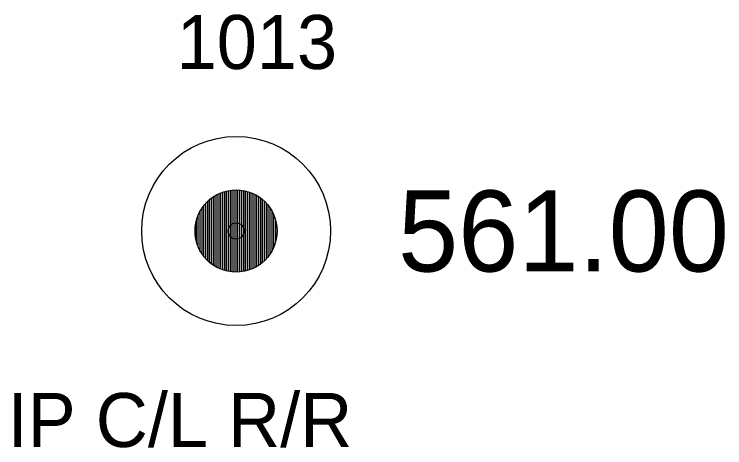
# Model space of a CAD drawing. Extents: x 1789242 to 1794757, y 908627 to 913936.
# Drawn here: x 1794743.37 to 1794756.54, y 912645.09 to 912653.12 of the extents above; entities that cross this region are included whole.
import ezdxf

# ---------------------------------------------------------------- set-up
doc = ezdxf.new("R2010")
doc.units = 0
for name, color, linetype in [('RD_EX_DV_Prop_txCode', 7, 'Continuous'), ('RD_EX_DV_PropPin', 7, 'Continuous'), ('RD_EX_TX_DV_Prop_ELEV', 7, 'Continuous'), ('RD_SMD_Locator', 7, 'Continuous')]:
    doc.layers.add(name, color=color, linetype=linetype)

msp = doc.modelspace()

# ---------------------------------------------------------------- linework, layer by layer
at = {"layer": 'RD_EX_DV_PropPin'}
for p, q in [((1794747.233, 912648.387), (1794747.233, 912649.828)), ((1794747.268, 912648.376), (1794747.268, 912649.839)), ((1794747.303, 912648.367), (1794747.303, 912649.848)), ((1794747.338, 912648.36), (1794747.338, 912649.856)), ((1794747.373, 912648.354), (1794747.373, 912649.861)), ((1794747.408, 912648.35), (1794747.408, 912649.865)), ((1794747.443, 912648.347), (1794747.443, 912649.868)), ((1794747.478, 912648.347), (1794747.478, 912649.869)), ((1794747.513, 912648.347), (1794747.513, 912649.868)), ((1794747.549, 912648.35), (1794747.549, 912649.865)), ((1794747.584, 912648.354), (1794747.584, 912649.861)), ((1794747.619, 912648.36), (1794747.619, 912649.856)), ((1794747.654, 912648.367), (1794747.654, 912649.848)), ((1794747.689, 912648.376), (1794747.689, 912649.839)), ((1794747.724, 912648.387), (1794747.724, 912649.828)), ((1794746.988, 912648.525), (1794746.988, 912649.69)), ((1794747.023, 912648.498), (1794747.023, 912649.717)), ((1794747.058, 912648.473), (1794747.058, 912649.742)), ((1794747.093, 912648.451), (1794747.093, 912649.764)), ((1794747.128, 912648.432), (1794747.128, 912649.783)), ((1794747.163, 912648.415), (1794747.163, 912649.8)), ((1794747.198, 912648.4), (1794747.198, 912649.815)), ((1794747.759, 912648.4), (1794747.759, 912649.815)), ((1794747.794, 912648.415), (1794747.794, 912649.8)), ((1794747.829, 912648.432), (1794747.829, 912649.783)), ((1794747.864, 912648.451), (1794747.864, 912649.764)), ((1794747.899, 912648.473), (1794747.899, 912649.742)), ((1794747.934, 912648.498), (1794747.934, 912649.717)), ((1794747.969, 912648.525), (1794747.969, 912649.69)), ((1794746.883, 912648.633), (1794746.883, 912649.582)), ((1794746.918, 912648.593), (1794746.918, 912649.623)), ((1794746.953, 912648.557), (1794746.953, 912649.658)), ((1794748.004, 912648.557), (1794748.004, 912649.658)), ((1794748.039, 912648.593), (1794748.039, 912649.623)), ((1794748.074, 912648.633), (1794748.074, 912649.582)), ((1794746.813, 912648.738), (1794746.813, 912649.477)), ((1794746.848, 912648.681), (1794746.848, 912649.534)), ((1794748.109, 912648.681), (1794748.109, 912649.534)), ((1794748.144, 912648.738), (1794748.144, 912649.477)), ((1794746.743, 912648.911), (1794746.743, 912649.304)), ((1794746.778, 912648.81), (1794746.778, 912649.406)), ((1794748.179, 912648.81), (1794748.179, 912649.406)), ((1794748.214, 912648.911), (1794748.214, 912649.304))]:
    msp.add_line(p, q, dxfattribs=at)
for radius in [1.75, 0.761]:
    msp.add_circle((1794747.478, 912649.108), radius, dxfattribs=at)
at = {"layer": 'RD_SMD_Locator'}
msp.add_circle((1794747.479, 912649.108), 0.15, dxfattribs=at)

# ---------------------------------------------------------------- texts
at = {"layer": 'RD_EX_DV_Prop_txCode'}
for s, p in [('1013', (1794746.376, 912652.108)), ('IP C/L R/R', (1794743.242, 912645.108))]:
    msp.add_text(s, height=1, dxfattribs=at).set_placement(p)
at = {"layer": 'RD_EX_TX_DV_Prop_ELEV'}
msp.add_text('561.00', height=1.5, dxfattribs=at).set_placement((1794750.479, 912648.358))

doc.saveas('drawing.dxf')
